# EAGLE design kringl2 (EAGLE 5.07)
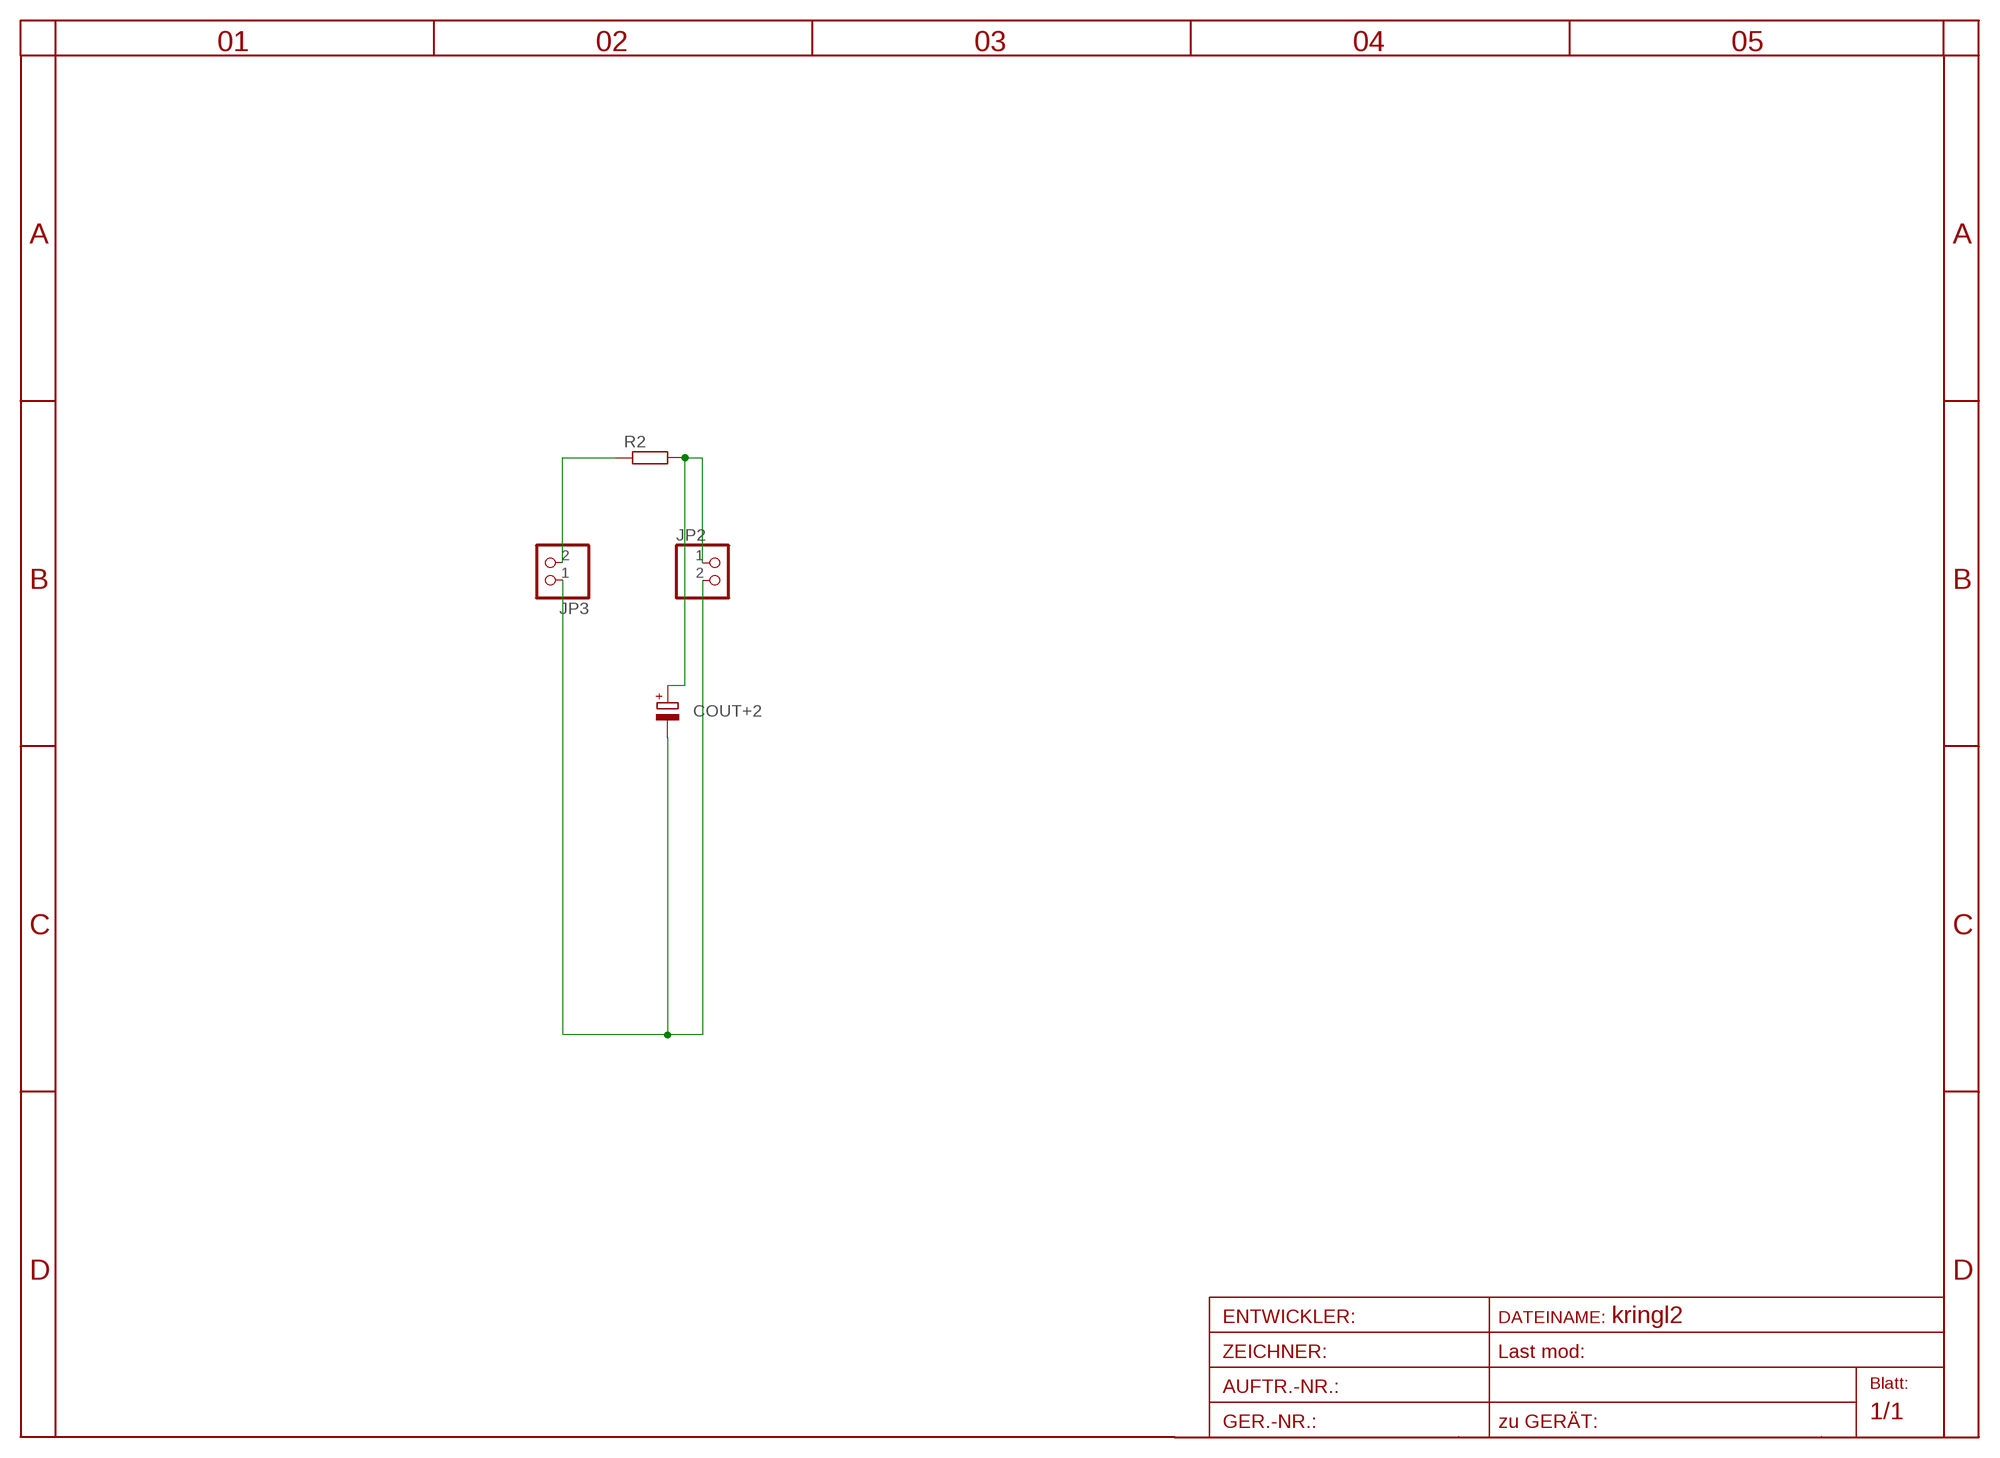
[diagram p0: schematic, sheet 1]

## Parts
COUT+2  CPOL-EUE3.5-8  [E3,5-8]
JP2  PINHD-1X2STR  [1X02]
JP3  PINHD-1X2STR  [1X02]
R2  R-EU_R2010  [R2010]

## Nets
N$1: JP3.2 R2.1
N$2: COUT+2.+ JP2.1 R2.2
N$7: COUT+2.- JP2.2 JP3.1

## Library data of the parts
COUT+2 = rcl:CPOL-EU: POLARIZED CAPACITOR, European symbol
JP2 JP3 = pinhead:PINHD-1X2: PIN HEADER
R2 = rcl:R-EU_: RESISTOR, European symbol

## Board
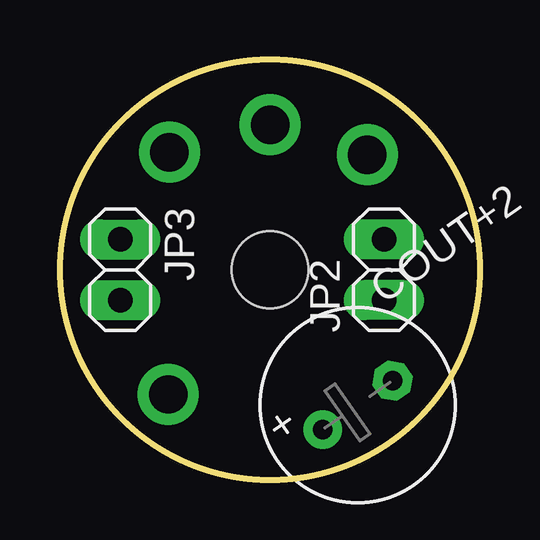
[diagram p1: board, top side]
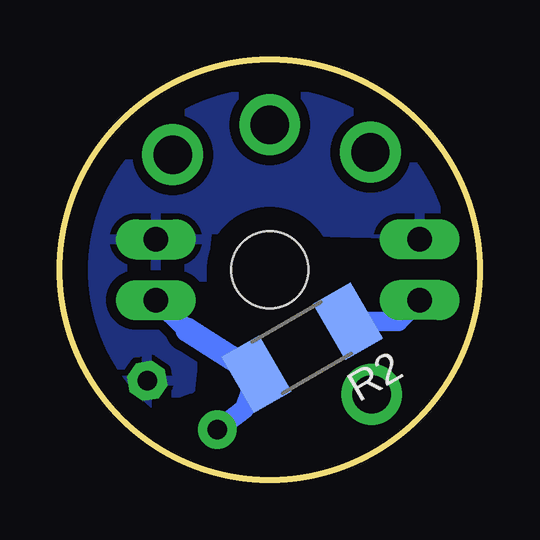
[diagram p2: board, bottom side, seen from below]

Size 17.5 x 17.5 mm. Coordinates in mm from the lower left corner, seen from the top.
Outline: circle at 8.75,8.75 radius 8.75
Copper layers (1*16): Top 0.035mm / dielectric 1.5mm / Bottom 0.035mm
Design rules "default *": minimum track width 10mil, minimum drill 20mil, track to track 8mil, track to pad 8mil, pad to pad 8mil, via to via 8mil, smd to smd 8mil, copper to edge 40mil, drill to drill 8mil, minimum pad ring 8mil, minimum via ring 8mil, stop-mask expansion 8mil, vias tented up to drill 0mil, thermal gap 10mil
Holes 3.2 mm at 8.75,8.75

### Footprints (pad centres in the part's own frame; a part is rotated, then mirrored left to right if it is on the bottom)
E3,5-8 = drill 0.813 pad 1.6 round: + -1.778,0 | drill 0.813 pad 1.6 octagon: - 1.778,0
1X02 = drill 1.016 pad 1.676 long: 1 -1.27,0; 2 1.27,0
R2010 = smd 1.8 x 2.7: 1 -2.2,0; 2 2.2,0

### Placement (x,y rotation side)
COUT+2  12.4,3.1 35 top
JP2  13.5,8.75 90 top
JP3  2.5,8.75 270 top
R2  7.4,5.5 210 bottom

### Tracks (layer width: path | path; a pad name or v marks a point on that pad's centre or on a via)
N$1
  Bottom 0.813: R2.1 3.38,6.6 JP3.2
N$2
  Bottom 0.813: 12.19,6.23 JP2.1 | R2.2 9.8,2.96 COUT+2.+
  Bottom 1.016: R2.2 12.19,6.23
N$7
  pour Bottom (isolate 0.406): 1.1,10.2 1.1,13.4 1.5,13.8 7.6,17.7 arc-133 14.3,3 12.05,3.8 11.35,10.45
N$14  (via drill 1.6 pad 2.54)
  other vias: 12.8,13.55
N$15  (via drill 1.6 pad 2.54)
  other vias: 8.75,14.8
N$16  (via drill 1.6 pad 2.54)
  other vias: 4.55,13.65
VPROT  (via drill 1.6 pad 2.54)
  other vias: 4.5,3.55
